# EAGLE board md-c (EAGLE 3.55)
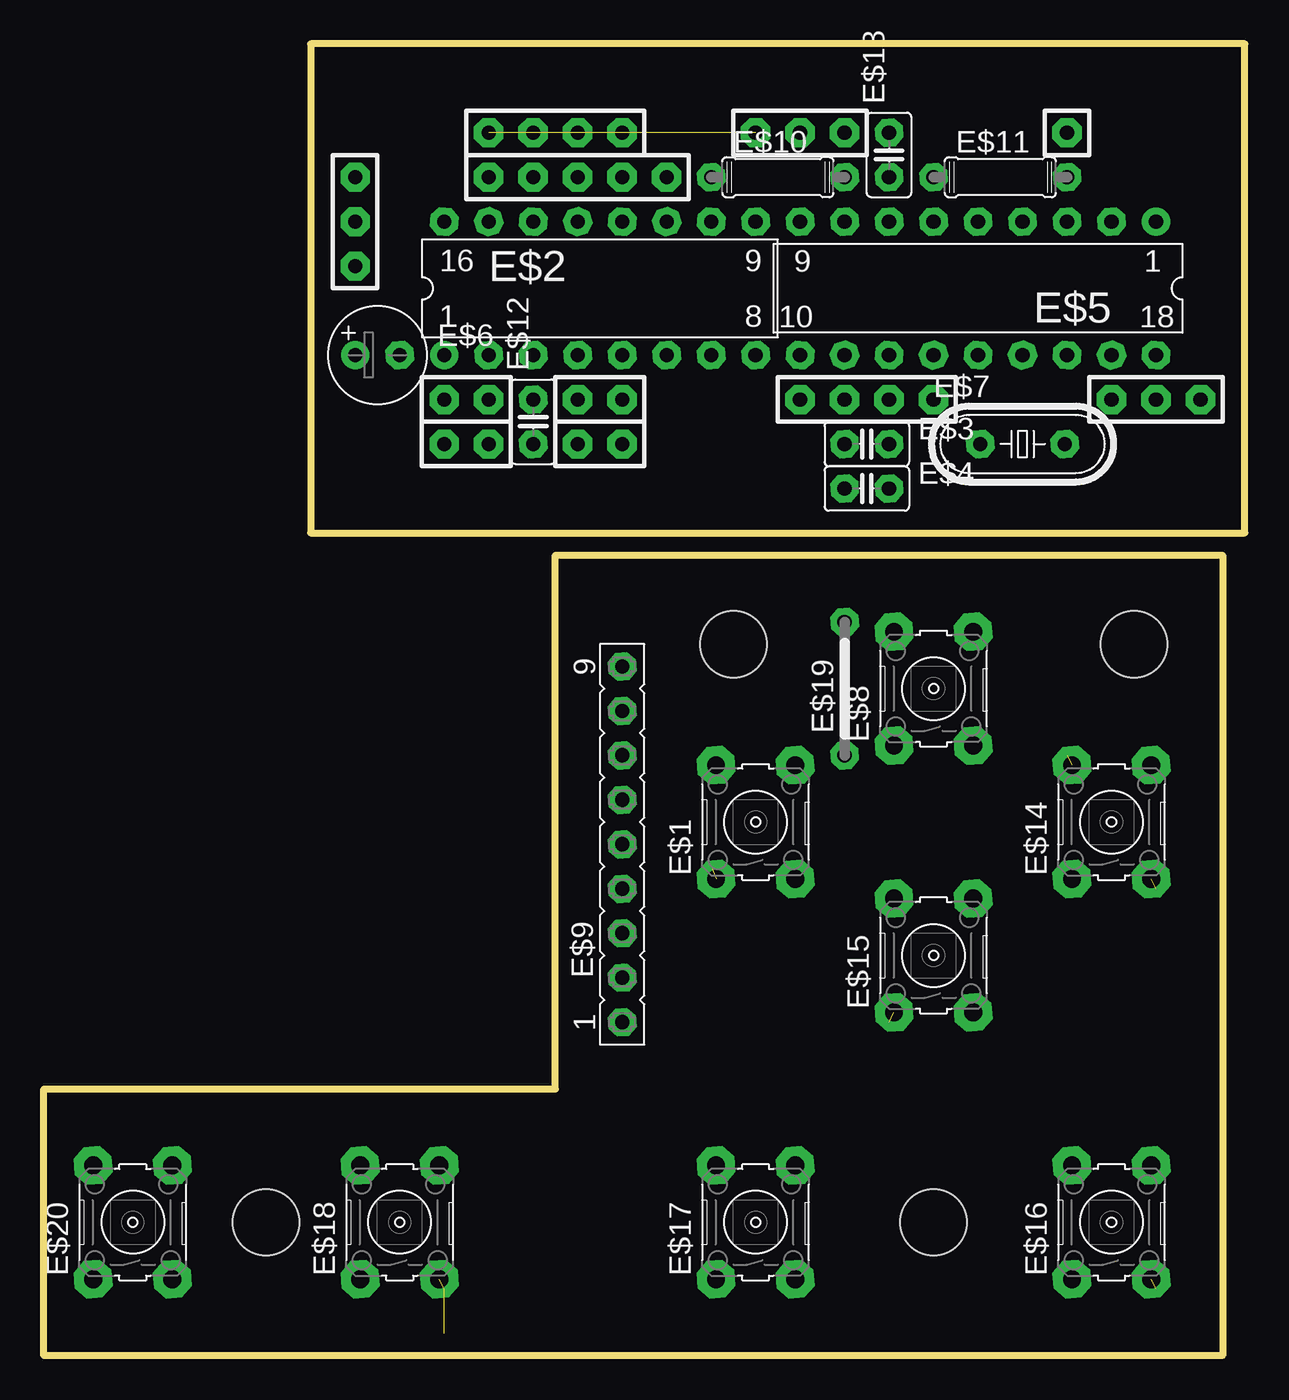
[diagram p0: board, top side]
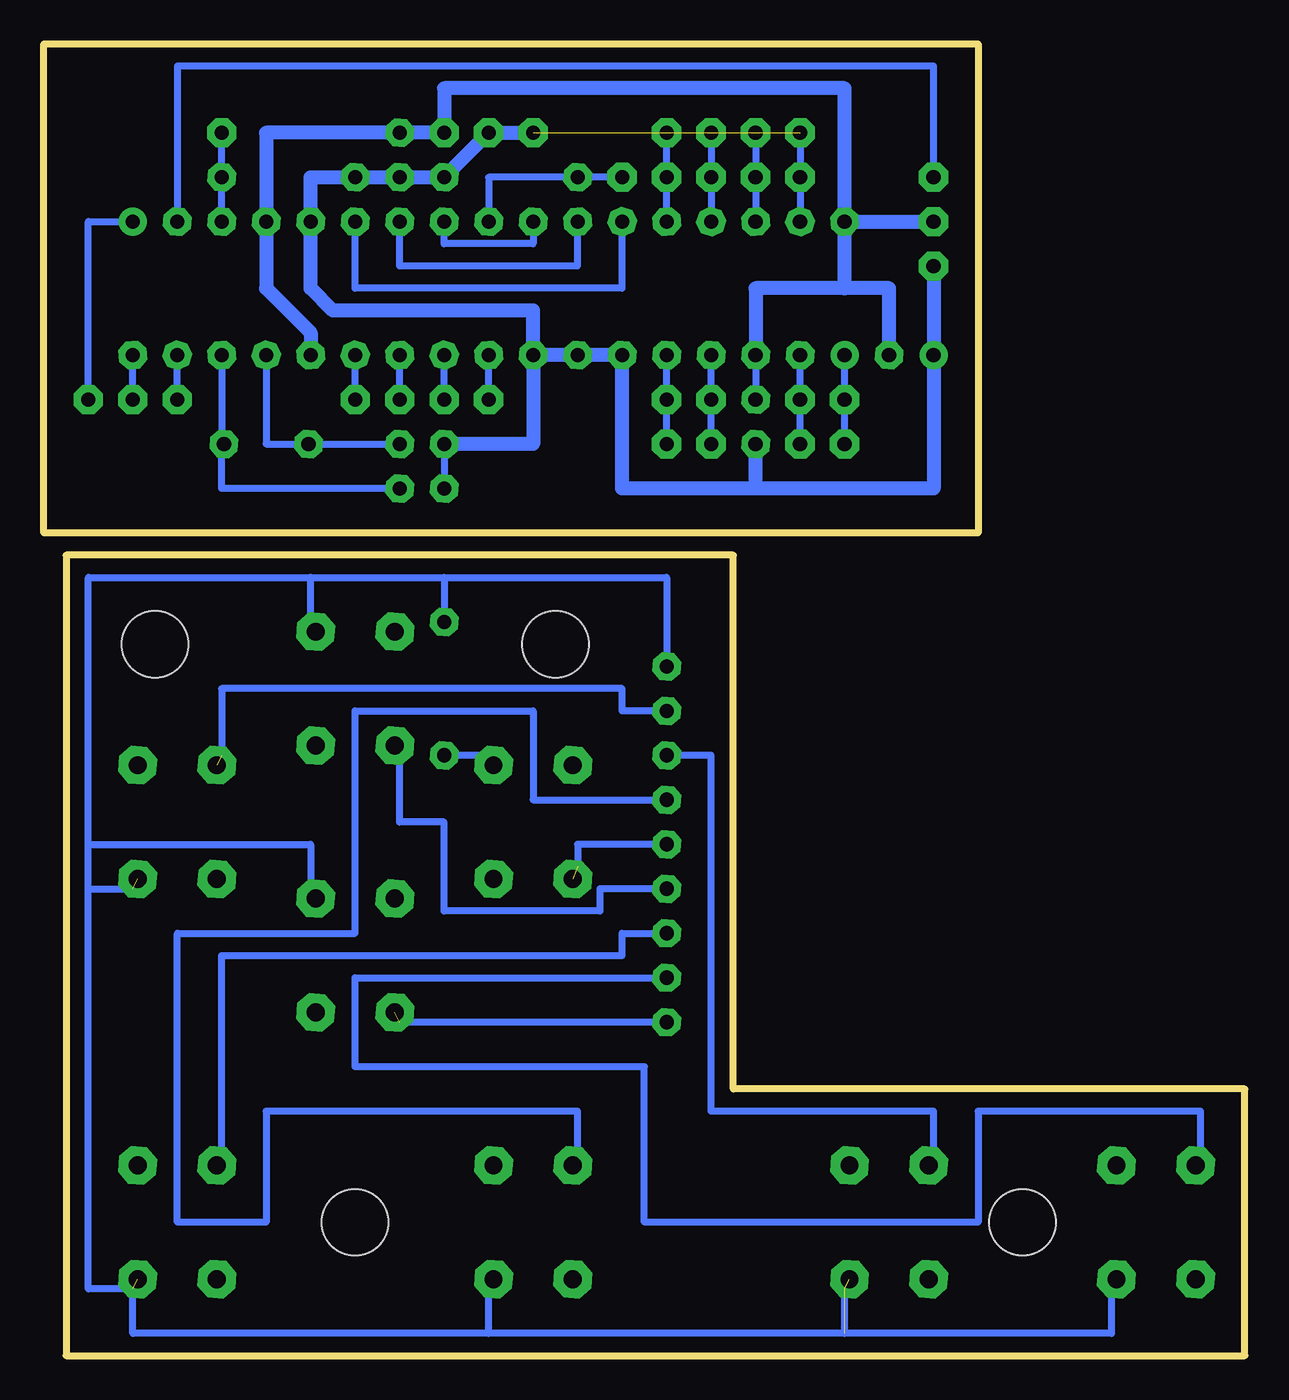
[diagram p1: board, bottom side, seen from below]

Size 68.58 x 74.93 mm. Coordinates in mm from the lower left corner, seen from the top.
Outline: 15.24,74.93 15.24,46.99 68.58,46.99 68.58,74.93 15.24,74.93
Outline: 29.21,15.24 29.21,45.72 67.31,45.72 67.31,0 0,0 0,15.24 29.21,15.24
Copper layers used: Bottom
Holes 3.81 mm at 39.37,40.64 62.23,40.64 12.7,7.62 50.8,7.62

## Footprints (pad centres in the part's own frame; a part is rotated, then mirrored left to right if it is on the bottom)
F-10XX = drill 1.016 pad 2.159 octagon:  -3.251,2.261;  -3.251,-2.261;  3.251,2.261;  3.251,-2.261
L16 = drill 0.813 pad 1.6 round:  -8.89,-3.81 | drill 0.813 pad 1.6 octagon:  -6.35,-3.81;  -3.81,-3.81;  -1.27,-3.81;  1.27,-3.81;  3.81,-3.81;  6.35,-3.81;  8.89,-3.81;  8.89,3.81;  6.35,3.81;  3.81,3.81;  1.27,3.81;  -1.27,3.81;  -3.81,3.81;  -6.35,3.81;  -8.89,3.81
,5-2 = drill 0.813 pad 1.6 octagon:  -1.27,0;  1.27,0
L18 = drill 0.813 pad 1.6 round:  -10.16,-3.81 | drill 0.813 pad 1.6 octagon:  -7.62,-3.81;  -5.08,-3.81;  -2.54,-3.81;  0,-3.81;  2.54,-3.81;  5.08,-3.81;  7.62,-3.81;  10.16,-3.81;  10.16,3.81;  7.62,3.81;  5.08,3.81;  2.54,3.81;  0,3.81;  -2.54,3.81;  -5.08,3.81;  -7.62,3.81;  -10.16,3.81
,5-6 = drill 0.813 pad 1.6 octagon:  1.27,0 | drill 0.813 pad 1.6 round:  -1.27,0
49/S = drill 0.813 pad 1.6 octagon:  -2.413,0;  2.413,0
09 = drill 0.813 pad 1.6 octagon:  -10.16,0;  -7.62,0;  -5.08,0;  -2.54,0;  0,0;  2.54,0;  5.08,0;  7.62,0;  10.16,0
07/7 = drill 0.813 pad 1.6 octagon:  -3.81,0;  3.81,0
 = drill 0.813 pad 1.6 octagon:  -3.81,0;  3.81,0

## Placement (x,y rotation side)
E$1  [F-10XX]  40.64,30.48 90 top
E$2  4051  [L16]  31.75,60.96 0 top
E$3  33p  [,5-2]  46.99,52.07 0 top
E$4  33p  [,5-2]  46.99,49.53 0 top
E$5  PIC16F84/10MHz  [L18]  53.34,60.96 180 top
E$6  47/16V  [,5-6]  19.05,57.15 0 top
E$7  10MHz  [49/S]  55.88,52.07 0 top
E$8  [F-10XX]  50.8,38.1 90 top
E$9  [09]  33.02,29.21 90 top
E$10  4k7  [07/7]  41.91,67.31 0 top
E$11  4k7  [07/7]  54.61,67.31 0 top
E$12  0.1  [,5-2]  27.94,53.34 90 top
E$13  0.1  [,5-2]  48.26,68.58 90 top
E$14  [F-10XX]  60.96,30.48 90 top
E$15  [F-10XX]  50.8,22.86 90 top
E$16  [F-10XX]  60.96,7.62 90 top
E$17  [F-10XX]  40.64,7.62 90 top
E$18  [F-10XX]  20.32,7.62 90 top
E$19  []  45.72,38.1 90 top
E$20  [F-10XX]  5.08,7.62 90 top

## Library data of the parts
E$1 E$8 E$14-E$18 E$20 = keyomron
E$2 = 40xx
E$3 E$4 E$12 E$13 = cap
E$5 = pic
E$6 = polcap
E$7 = quartz
E$9 = con-lsta
E$10 E$11 = r
E$19 = jumper

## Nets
S$1: E$5.
S$2: E$2. E$5. E$6. E$12. E$13.
S$3: E$3. E$5. E$7.
S$4: E$4. E$5. E$7.
S$5: E$9. E$16.
S$6: E$2.
S$7: E$2.
S$8: E$2. E$5.
S$9: E$2. E$5.
S$10: E$2.
S$11: E$2.
S$12: E$2. E$5.
S$13: E$8. E$9. E$14. E$15. E$16. E$17. E$18. E$19. E$20.
S$14: E$5.
S$15: E$5.
S$16: E$5.
S$17: E$5.
S$18: E$5.
S$19: E$5.
S$20: E$5.
S$21: E$5. E$11.
S$22: E$2. E$3. E$4. E$5. E$6. E$10. E$11. E$12. E$13.
S$23: E$1. E$19.
S$24: E$9. E$18.
S$25: E$9. E$20.
S$26: E$9. E$15.
S$27: E$9. E$14.
S$28: E$2.
S$29: E$5. E$10.
S$30: E$9. E$17.
S$31: E$1. E$9.
S$32: E$8. E$9.

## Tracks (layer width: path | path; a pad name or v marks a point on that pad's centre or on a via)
S$1  (via drill 0.81 pad 1.68)
  Bottom 0.406: v17.78,67.31 17.78,73.66 60.96,73.66 60.96,64.77
S$2  (via drill 0.81 pad 1.68)
  Bottom 0.406: 27.94,57.15 E$12.
  Bottom 0.813: E$2. v17.78,64.77 | E$2. 22.86,72.39 45.72,72.39 v45.72,69.85 E$13. 55.88,69.85 55.88,64.77 55.88,60.96 53.34,58.42 53.34,57.15 | 22.86,60.96 E$2. | 22.86,60.96 27.94,60.96 27.94,57.15 | 20.32,57.15 20.32,60.96 22.86,60.96
S$3
  Bottom 0.406: 55.88,57.15 55.88,52.07 53.47,52.07 | 53.34,52.07 53.47,52.07 | 53.47,52.07 E$3.
S$4
  Bottom 0.406: E$4. 58.42,49.53 58.42,52.07 | 58.42,52.07 E$7. | 58.42,57.15 58.42,52.07
S$5
  Bottom 0.406: 58.7,10.87 58.42,10.87 58.42,22.86 35.56,22.86 35.56,24.13 33.02,24.13
S$6  (via drill 0.81 pad 1.68)
  Bottom 0.406: v22.86,52.07 v22.86,54.61 22.86,57.15
S$7  (via drill 0.81 pad 1.68)
  Bottom 0.406: 25.4,57.15 v25.4,54.61 v25.4,52.07
S$8
  Bottom 0.406: 40.64,64.77 40.64,63.5 45.72,63.5 45.72,64.77
S$9
  Bottom 0.406: 48.26,64.77 48.26,62.23 38.1,62.23 38.1,64.77
S$10  (via drill 0.81 pad 1.68)
  Bottom 0.406: v30.48,52.07 v30.48,54.61 30.48,57.15
S$11  (via drill 0.81 pad 1.68)
  Bottom 0.406: v33.02,52.07 v33.02,54.61 33.02,57.15
S$12
  Bottom 0.406: 35.56,64.77 35.56,60.96 50.8,60.96 50.8,64.77
S$13  (5 unrouted)
  Bottom 0.406: E$15. 53.34,26.11 53.34,29.21 66.04,29.21 | 66.04,26.67 66.04,29.21 | 66.04,26.67 63.5,26.67 | 66.04,26.67 66.04,3.81 63.5,3.81 | 63.22,4.37 63.5,4.37 63.5,3.81 | 22.58,4.37 22.86,4.37 22.86,3.81 22.86,1.27 | 42.9,4.37 43.18,4.37 43.18,1.27 | 63.5,3.81 63.5,1.27 43.18,1.27 | 22.86,1.27 43.18,1.27 | 7.34,4.37 7.62,4.37 7.62,1.27 22.86,1.27 | 45.72,44.45 33.02,44.45 E$9. | 53.34,44.45 66.04,44.45 66.04,29.21 | E$8. 53.34,41.35 53.34,44.45 | 53.34,44.45 45.72,44.45 | 45.72,44.45 E$19.
S$14  (via drill 0.81 pad 1.68)
  Bottom 0.406: v43.18,54.61 43.18,57.15
S$15  (via drill 0.81 pad 1.68)
  Bottom 0.406: v45.72,54.61 45.72,57.15
S$16  (via drill 0.81 pad 1.68)
  Bottom 0.406: v48.26,54.61 48.26,57.15
S$17  (via drill 0.81 pad 1.68)
  Bottom 0.406: v50.8,54.61 50.8,57.15
S$18  (via drill 0.81 pad 1.68)
  Bottom 0.406: v60.96,54.61 60.96,57.15
S$19  (via drill 0.81 pad 1.68)
  Bottom 0.406: v63.5,54.61 E$5.
S$20  (via drill 0.81 pad 1.68)
  Bottom 0.406: v66.04,54.61 66.04,64.77 63.5,64.77
S$21  (via drill 0.81 pad 1.68)
  Bottom 0.406: 58.42,64.77 E$11. v58.42,69.85
S$22  (via drill 0.81 pad 1.68)  (3 unrouted)
  Bottom 0.406: 25.4,64.77 v25.4,67.31 v25.4,69.85 | 27.94,64.77 v27.94,67.31 v27.94,69.85 | 30.48,64.77 v30.48,67.31 v30.48,69.85 | 45.72,52.07 45.72,49.53
  Bottom 0.813: v40.64,69.85 v43.18,69.85 E$10. 48.26,67.31 50.8,67.31 53.34,67.31 53.34,64.77 53.34,60.96 52.07,59.69 40.64,59.69 40.64,57.15 | 45.72,52.07 40.64,52.07 40.64,57.15 | 40.64,57.15 38.1,57.15 35.56,57.15 35.56,49.53 27.94,49.53 | 27.94,49.53 27.94,52.07 | 27.94,49.53 17.78,49.53 E$6. v17.78,62.23
S$23
  Bottom 0.406: E$1. 43.18,33.73 43.18,34.29 45.72,34.29
S$24
  Bottom 0.406: 18.06,10.87 17.78,10.87 17.78,13.97 30.48,13.97 30.48,34.29 33.02,34.29
S$25
  Bottom 0.406: 2.82,10.87 2.54,10.87 2.54,13.97 15.24,13.97 15.24,7.62 34.29,7.62 34.29,16.51 50.8,16.51 50.8,21.59 33.02,21.59
S$26  (1 unrouted)
  Bottom 0.406: 33.02,19.05 48.26,19.05
S$27  (1 unrouted)
  Bottom 0.406: 33.02,36.83 35.56,36.83 35.56,38.1 58.42,38.1 58.42,34.29
S$28  (via drill 0.81 pad 1.68)
  Bottom 0.406: v33.02,69.85 v33.02,67.31 33.02,64.77
S$29  (via drill 0.81 pad 1.68)
  Bottom 0.406: v35.56,67.31 38.1,67.31 43.18,67.31 43.18,64.77
S$30
  Bottom 0.406: 38.38,10.87 38.1,10.87 38.1,13.97 55.88,13.97 55.88,7.62 60.96,7.62 60.96,24.13 50.8,24.13 50.8,36.83 40.64,36.83 40.64,31.75 33.02,31.75
S$31  (1 unrouted)
  Bottom 0.406: 33.02,29.21 38.1,29.21 38.1,27.94
S$32
  Bottom 0.406: 33.02,26.67 36.83,26.67 36.83,25.4 45.72,25.4 45.72,30.48 48.26,30.48 48.26,34.85 48.54,34.85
